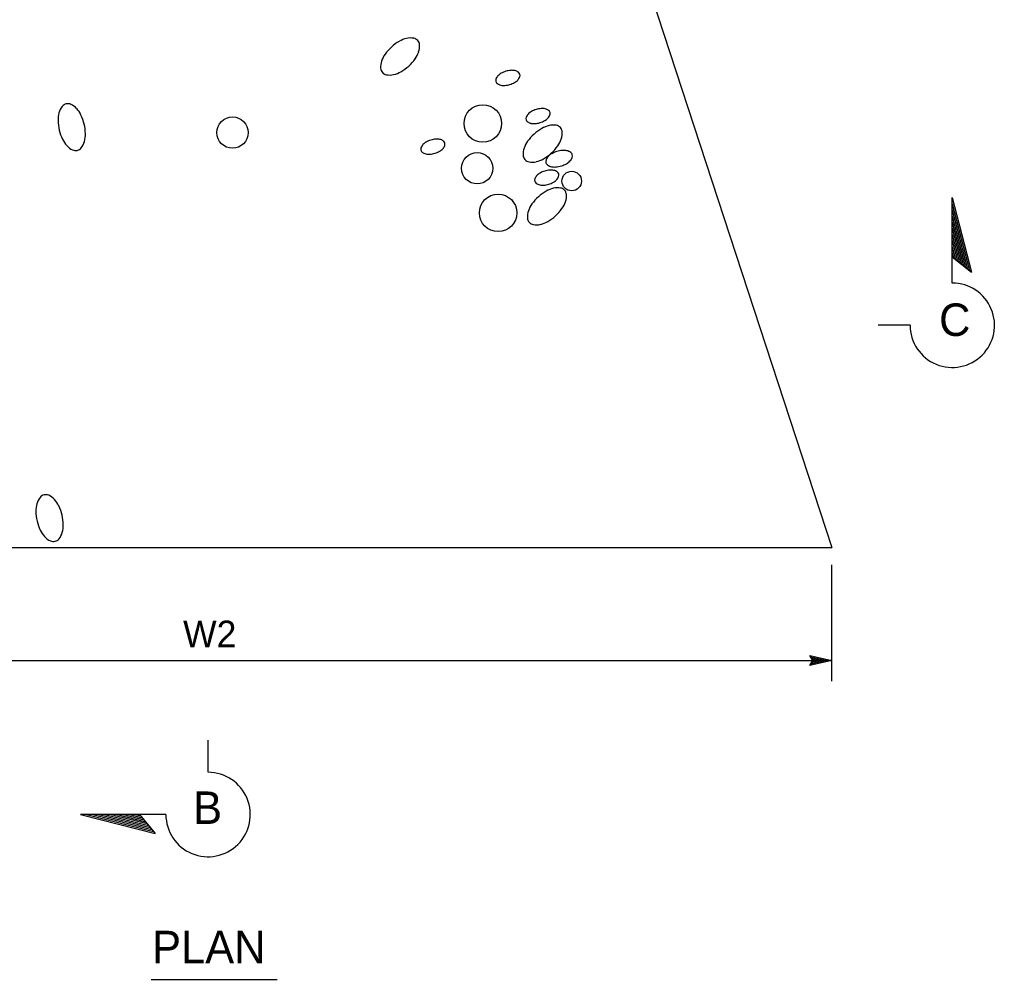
# Model space of a CAD drawing. Extents: x 6707692 to 6708868, y 1870875 to 1871658.
# Drawn here: x 6707917.2 to 6708133.7, y 1870974.5 to 1871187.6 of the extents above; entities that cross this region are included whole.
import ezdxf

# ---------------------------------------------------------------- set-up
doc = ezdxf.new("R2010")
doc.units = 0
doc.layers.add('Level 60', color=7, linetype='Continuous')

msp = doc.modelspace()

# ---------------------------------------------------------------- linework, layer by layer
at = {"layer": 'Level 60'}
for p, q in [((6708003.22, 1871358.74), (6708097.63, 1871070.4)), ((6708124.35, 1871148.07), (6708128.57, 1871131.51)), ((6708124.35, 1871129.1), (6708124.35, 1871148.07)), ((6708124.35, 1871146.71), (6708128.13, 1871131.87)), ((6708124.35, 1871145.35), (6708127.7, 1871132.22)), ((6708124.35, 1871143.99), (6708127.26, 1871132.58)), ((6708124.35, 1871142.63), (6708126.82, 1871132.93)), ((6708124.35, 1871141.27), (6708126.38, 1871133.29)), ((6708124.35, 1871139.9), (6708125.94, 1871133.64)), ((6708124.35, 1871138.54), (6708125.51, 1871133.99)), ((6708124.35, 1871137.18), (6708125.07, 1871134.35)), ((6708124.35, 1871135.82), (6708124.63, 1871134.7)), ((6708124.35, 1871134.93), (6708128.57, 1871131.51)), ((6708114.98, 1871119.74), (6708107.86, 1871119.74)), ((6708107.88, 1871119.7), (6708107.88, 1871119.7)), ((6708097.63, 1871040.71), (6708097.63, 1871066.56)), ((6708093.37, 1871045.32), (6708092.72, 1871046.42)), ((6708092.72, 1871046.42), (6708092.72, 1871046.42)), ((6708092.72, 1871046.42), (6708097.63, 1871045.32)), ((6707819.35, 1871045.32), (6708097.63, 1871045.32)), ((6708097.63, 1871045.32), (6708092.72, 1871044.23)), ((6708092.72, 1871044.23), (6708093.37, 1871045.32)), ((6708092.72, 1871044.23), (6708092.72, 1871044.23)), ((6708092.89, 1871046.12), (6708096.5, 1871045.32)), ((6708096.49, 1871045.31), (6708092.91, 1871044.52)), ((6708095.37, 1871045.32), (6708093.06, 1871044.81)), ((6708093.09, 1871045.83), (6708095.37, 1871045.32)), ((6708093.23, 1871045.54), (6708094.24, 1871045.32)), ((6708094.24, 1871045.32), (6708093.25, 1871045.1)), ((6708097.63, 1871045.32), (6708095.84, 1871045.32)), ((6708097.63, 1871045.32), (6708097.63, 1871045.32)), ((6707959.1, 1871020.5), (6707959.1, 1871027.63)), ((6707949.74, 1871011.14), (6707930.77, 1871011.14)), ((6707930.77, 1871011.14), (6707947.33, 1871006.91)), ((6707932.13, 1871011.14), (6707946.97, 1871007.35)), ((6707933.49, 1871011.14), (6707946.62, 1871007.79)), ((6707934.85, 1871011.14), (6707946.26, 1871008.23)), ((6707936.21, 1871011.14), (6707945.91, 1871008.66)), ((6707937.57, 1871011.14), (6707945.55, 1871009.1)), ((6707938.94, 1871011.14), (6707945.2, 1871009.54)), ((6707940.3, 1871011.14), (6707944.85, 1871009.98)), ((6707941.66, 1871011.14), (6707944.49, 1871010.41)), ((6707943.02, 1871011.14), (6707944.14, 1871010.85)), ((6707943.91, 1871011.14), (6707947.33, 1871006.91)), ((6707949.74, 1871011.05), (6707949.74, 1871011.05)), ((6707946.47, 1870974.51), (6707974.44, 1870974.51))]:
    msp.add_line(p, q, dxfattribs=at)
msp.add_lwpolyline([(6707819.35, 1871070.4), (6708097.63, 1871070.4)], dxfattribs=at)
for centre, radius in [((6708020.1, 1871164.53), 4.16), ((6707964.53, 1871162.5), 3.47), ((6708018.85, 1871154.58), 3.47), ((6708039.84, 1871151.75), 2.16), ((6708023.5, 1871144.68), 4.16)]:
    msp.add_circle(centre, radius, dxfattribs=at)
for centre, radius, start, end in [((6708006.41, 1871174.22), 9.82, 119.5633, 132.123), ((6708004.67, 1871177.3), 6.29, 103.8489, 119.5633), ((6708004.08, 1871179.69), 3.82, 79.7233, 103.8489), ((6708004.47, 1871181.87), 1.61, 42.123, 79.7233), ((6708004.47, 1871181.87), 1.61, 4.5228, 42.123), ((6708006.41, 1871174.22), 9.82, 132.123, 144.6828), ((6708002.26, 1871181.69), 3.82, 340.3972, 4.5228), ((6708001.21, 1871177.09), 3.82, 160.3972, 184.5228), ((6708003.53, 1871176.26), 6.29, 144.6828, 160.3972), ((6707997.06, 1871184.56), 9.82, 312.123, 324.6828), ((6707999.94, 1871182.52), 6.29, 324.6828, 340.3972), ((6707999, 1871176.92), 1.61, 184.5228, 222.123), ((6707997.06, 1871184.56), 9.82, 299.5633, 312.123), ((6708026.68, 1871171.32), 5.01, 94.1096, 107.0018), ((6708026.56, 1871173.08), 3.25, 78.0776, 94.1096), ((6708026.81, 1871174.29), 2.01, 53.8569, 78.0776), ((6707999, 1871176.92), 1.61, 222.123, 259.7233), ((6707999.39, 1871179.1), 3.82, 259.7233, 283.8489), ((6707998.8, 1871181.49), 6.29, 283.8489, 299.5633), ((6708023.86, 1871174.09), 0.886, 160.1467, 197.0018), ((6708024.91, 1871173.71), 2.01, 135.926, 160.1467), ((6708025.8, 1871172.85), 3.25, 119.894, 135.926), ((6708026.68, 1871171.32), 5.01, 107.0018, 119.894), ((6708025.53, 1871176.44), 3.25, 299.894, 315.926), ((6708026.42, 1871175.58), 2.01, 315.926, 340.1467), ((6708027.48, 1871175.2), 0.886, 17.0018, 53.8569), ((6708027.48, 1871175.2), 0.886, 340.1467, 17.0018), ((6708023.86, 1871174.09), 0.886, 197.0018, 233.8569), ((6708024.52, 1871175), 2.01, 233.8569, 258.0776), ((6708024.77, 1871176.21), 3.25, 258.0776, 274.1096), ((6708024.65, 1871177.97), 5.01, 274.1096, 287.0018), ((6708024.65, 1871177.97), 5.01, 287.0018, 299.894), ((6707929.69, 1871165.92), 3.82, 140.9226, 165.0482), ((6707927.97, 1871167.31), 1.61, 103.3223, 140.9226), ((6707927.97, 1871167.31), 1.61, 65.722, 103.3223), ((6707927.06, 1871165.29), 3.82, 41.5964, 65.722), ((6707925.22, 1871163.66), 6.29, 25.8821, 41.5964), ((6708033.39, 1871162.84), 5.01, 107.0018, 119.894), ((6708033.39, 1871162.84), 5.01, 94.1096, 107.0018), ((6708033.26, 1871164.6), 3.25, 78.0776, 94.1096), ((6708033.52, 1871165.81), 2.01, 53.8569, 78.0776), ((6707932.07, 1871165.28), 6.29, 165.0482, 180.7625), ((6707922.04, 1871162.12), 9.82, 13.3223, 25.8821), ((6708030.56, 1871165.62), 0.886, 160.1467, 197.0018), ((6708030.56, 1871165.62), 0.886, 197.0018, 233.8569), ((6708031.62, 1871165.23), 2.01, 135.926, 160.1467), ((6708032.51, 1871164.37), 3.25, 119.894, 135.926), ((6708032.24, 1871167.97), 3.25, 299.894, 315.926), ((6708033.12, 1871167.11), 2.01, 315.926, 340.1467), ((6708034.18, 1871166.72), 0.886, 17.0018, 53.8569), ((6708034.18, 1871166.72), 0.886, 340.1467, 17.0018), ((6707935.61, 1871165.33), 9.82, 180.7625, 193.3223), ((6707922.04, 1871162.12), 9.82, 0.7625, 13.3223), ((6708031.23, 1871166.53), 2.01, 233.8569, 258.0776), ((6708031.48, 1871167.74), 3.25, 258.0776, 274.1096), ((6708038.07, 1871154.89), 9.82, 119.5633, 132.123), ((6708031.36, 1871169.5), 5.01, 274.1096, 287.0018), ((6708031.36, 1871169.5), 5.01, 287.0018, 299.894), ((6708036.33, 1871157.96), 6.29, 103.8489, 119.5633), ((6708035.74, 1871160.36), 3.82, 79.7233, 103.8489), ((6708036.13, 1871162.54), 1.61, 42.123, 79.7233), ((6708036.13, 1871162.54), 1.61, 4.5228, 42.123), ((6707935.61, 1871165.33), 9.82, 193.3223, 205.8821), ((6707932.43, 1871163.79), 6.29, 205.8821, 221.5964), ((6707925.57, 1871162.16), 6.29, 345.0482, 0.7625), ((6708010.02, 1871156.06), 5.01, 94.1096, 107.0018), ((6708009.9, 1871157.82), 3.25, 78.0776, 94.1096), ((6708038.07, 1871154.89), 9.82, 132.123, 144.6828), ((6708031.6, 1871163.19), 6.29, 324.6828, 340.3972), ((6708033.92, 1871162.36), 3.82, 340.3972, 4.5228), ((6707930.59, 1871162.15), 3.82, 221.5964, 245.722), ((6707929.68, 1871160.13), 1.61, 283.3223, 320.9226), ((6707927.96, 1871161.53), 3.82, 320.9226, 345.0482), ((6708007.2, 1871158.83), 0.886, 160.1467, 197.0018), ((6708008.26, 1871158.45), 2.01, 135.926, 160.1467), ((6708009.15, 1871157.59), 3.25, 119.894, 135.926), ((6708010.02, 1871156.06), 5.01, 107.0018, 119.894), ((6708008.87, 1871161.18), 3.25, 299.894, 315.926), ((6708010.15, 1871159.03), 2.01, 53.8569, 78.0776), ((6708009.76, 1871160.32), 2.01, 315.926, 340.1467), ((6708010.82, 1871159.94), 0.886, 17.0018, 53.8569), ((6708010.82, 1871159.94), 0.886, 340.1467, 17.0018), ((6708032.87, 1871157.76), 3.82, 160.3972, 184.5228), ((6708035.19, 1871156.93), 6.29, 144.6828, 160.3972), ((6708028.72, 1871165.23), 9.82, 312.123, 324.6828), ((6707929.68, 1871160.13), 1.61, 245.722, 283.3223), ((6708007.2, 1871158.83), 0.886, 197.0018, 233.8569), ((6708007.86, 1871159.74), 2.01, 233.8569, 258.0776), ((6708008.12, 1871160.95), 3.25, 258.0776, 274.1096), ((6708007.99, 1871162.71), 5.01, 274.1096, 287.0018), ((6708007.99, 1871162.71), 5.01, 287.0018, 299.894), ((6708030.66, 1871157.59), 1.61, 184.5228, 222.123), ((6708028.72, 1871165.23), 9.82, 299.5633, 312.123), ((6708036.22, 1871155.68), 2.21, 135.926, 160.1467), ((6708037.2, 1871154.74), 3.57, 119.894, 135.926), ((6708038.16, 1871153.05), 5.51, 107.0018, 119.894), ((6708038.16, 1871153.05), 5.51, 94.1096, 107.0018), ((6708038.02, 1871154.99), 3.57, 78.0776, 94.1096), ((6708038.31, 1871156.32), 2.21, 53.8569, 78.0776), ((6708037.87, 1871157.74), 2.21, 315.926, 340.1467), ((6708039.04, 1871157.32), 0.975, 17.0018, 53.8569), ((6708039.04, 1871157.32), 0.975, 340.1467, 17.0018), ((6708030.66, 1871157.59), 1.61, 222.123, 259.7233), ((6708031.05, 1871159.76), 3.82, 259.7233, 283.8489), ((6708030.46, 1871162.16), 6.29, 283.8489, 299.5633), ((6708035.05, 1871156.1), 0.975, 160.1467, 197.0018), ((6708035.05, 1871156.1), 0.975, 197.0018, 233.8569), ((6708035.78, 1871157.1), 2.21, 233.8569, 258.0776), ((6708036.07, 1871158.43), 3.57, 258.0776, 274.1096), ((6708035.93, 1871160.37), 5.51, 274.1096, 287.0018), ((6708035.93, 1871160.37), 5.51, 287.0018, 299.894), ((6708036.89, 1871158.69), 3.57, 299.894, 315.926), ((6708033.55, 1871151.57), 2.01, 135.926, 160.1467), ((6708034.43, 1871150.71), 3.25, 119.894, 135.926), ((6708035.31, 1871149.18), 5.01, 107.0018, 119.894), ((6708035.31, 1871149.18), 5.01, 94.1096, 107.0018), ((6708035.19, 1871150.94), 3.25, 78.0776, 94.1096), ((6708035.44, 1871152.15), 2.01, 53.8569, 78.0776), ((6708035.05, 1871153.44), 2.01, 315.926, 340.1467), ((6708036.11, 1871153.06), 0.886, 17.0018, 53.8569), ((6708036.11, 1871153.06), 0.886, 340.1467, 17.0018), ((6708032.49, 1871151.95), 0.886, 160.1467, 197.0018), ((6708032.49, 1871151.95), 0.886, 197.0018, 233.8569), ((6708033.15, 1871152.86), 2.01, 233.8569, 258.0776), ((6708033.41, 1871154.07), 3.25, 258.0776, 274.1096), ((6708033.28, 1871155.83), 5.01, 274.1096, 287.0018), ((6708033.28, 1871155.83), 5.01, 287.0018, 299.894), ((6708036.69, 1871146.44), 3.82, 79.7233, 103.8489), ((6708034.16, 1871154.3), 3.25, 299.894, 315.926), ((6708037.08, 1871148.62), 1.61, 42.123, 79.7233), ((6708039.02, 1871140.98), 9.82, 132.123, 144.6828), ((6708039.02, 1871140.98), 9.82, 119.5633, 132.123), ((6708037.28, 1871144.05), 6.29, 103.8489, 119.5633), ((6708037.08, 1871148.62), 1.61, 4.5228, 42.123), ((6708034.87, 1871148.45), 3.82, 340.3972, 4.5228), ((6708036.14, 1871143.02), 6.29, 144.6828, 160.3972), ((6708032.55, 1871149.27), 6.29, 324.6828, 340.3972), ((6708033.82, 1871143.85), 3.82, 160.3972, 184.5228), ((6708029.67, 1871151.32), 9.82, 299.5633, 312.123), ((6708029.67, 1871151.32), 9.82, 312.123, 324.6828), ((6708031.61, 1871143.67), 1.61, 184.5228, 222.123), ((6708031.61, 1871143.67), 1.61, 222.123, 259.7233), ((6708032, 1871145.85), 3.82, 259.7233, 283.8489), ((6708031.41, 1871148.24), 6.29, 283.8489, 299.5633), ((6708124.35, 1871119.74), 9.37, 179.9995, 90), ((6707924.78, 1871079.13), 3.82, 140.9226, 165.0482), ((6707923.06, 1871080.52), 1.61, 103.3223, 140.9226), ((6707923.06, 1871080.52), 1.61, 65.722, 103.3223), ((6707922.15, 1871078.51), 3.82, 41.5964, 65.722), ((6707920.31, 1871076.87), 6.29, 25.8821, 41.5964), ((6707927.16, 1871078.49), 6.29, 165.0482, 180.7625), ((6707917.13, 1871075.33), 9.82, 13.3223, 25.8821), ((6707930.69, 1871078.54), 9.82, 180.7625, 193.3223), ((6707917.13, 1871075.33), 9.82, 0.7625, 13.3223), ((6707930.69, 1871078.54), 9.82, 193.3223, 205.8821), ((6707920.66, 1871075.38), 6.29, 345.0482, 0.7625), ((6707927.51, 1871077), 6.29, 205.8821, 221.5964), ((6707925.67, 1871075.36), 3.82, 221.5964, 245.722), ((6707924.76, 1871073.34), 1.61, 283.3223, 320.9226), ((6707923.04, 1871074.74), 3.82, 320.9226, 345.0482), ((6707924.76, 1871073.34), 1.61, 245.722, 283.3223), ((6707959.1, 1871011.13), 9.37, 180, 90.0005)]:
    msp.add_arc(centre, radius, start, end, dxfattribs=at)

# ---------------------------------------------------------------- texts
for s, height, p in [('C', 7.21, (6708121.41, 1871117.36)), ('W2', 5.9, (6707953.55, 1871048.27)), ('B', 7.21, (6707955.79, 1871009.04)), ('PLAN', 7.211, (6707946.67, 1870978.11))]:
    msp.add_text(s, height=height, dxfattribs=at).set_placement(p)

doc.saveas('drawing.dxf')
